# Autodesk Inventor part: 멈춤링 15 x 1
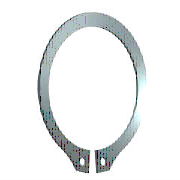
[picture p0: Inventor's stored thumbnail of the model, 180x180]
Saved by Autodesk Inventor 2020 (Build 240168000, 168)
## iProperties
Created: 2012-02
Part Number: 멈춤링 15 x 1
Material: 강철, 연강
Description: 리테이닝 링(C형)
Document SubType Name: Modeling
Standard: KS B 1336
Designer: mduedu
Standards Organization: KS
Language: ko-KR
Size Designation: 15 x 1
Categories: <MemberInstance><Categories><Category DisplayName="샤프트 부품" InternalName="7f7aeb1f-a693-4053-b835-cee3144e0d98" Mnemonic="SHFT"><Category DisplayName="써클립" Inter
Density: 1 g/cm^3
Appearance: 파란색 - 벽 페인트 - 광택
IsCustomPart: 1
Author: mduedu
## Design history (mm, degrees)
sketch "스케치1"
  geometry: L1 (-6, 0)-(6, 0) reference; L2 (0, 20.189)-(0, -80.536) reference; L3 (-48.09, 0)-(48.09, 0) reference; L4 (-0.425, -14.637)-(-0.425, -18.137); L5 (-0.425, -6.54)-(-0.425, -13.29); L6 (-2.795, 2.1)-(3.672, 2.1); L7 (0.425, -6.54)-(0.425, -13.29); L8 (0.425, -14.637)-(0.425, -18.137); C1 r 0.85 at (-1.7, -16.283); C2 r 0.85 at (1.7, -16.283); A1 r 7.15 centre (0, -7.5) between (0.425, -14.637) and (-0.425, -14.637); A2 r 9.075 centre (0, -6.975) between (4.291, -14.971) and (-4.291, -14.971); A3 r 10.646 centre (0, -7.5) between (-2.023, -17.952) and (-0.425, -18.137); A4 r 1.7 centre (-1.7, -16.283) between (-3.397, -16.376) and (-2.023, -17.952); A5 r 1.7 centre (-5.095, -16.469) between (-3.397, -16.376) and (-4.291, -14.971); A6 r 1.7 centre (5.095, -16.469) between (4.291, -14.971) and (3.397, -16.376); A7 r 1.7 centre (1.7, -16.283) between (2.023, -17.952) and (3.397, -16.376); A8 r 10.646 centre (0, -7.5) between (0.425, -18.137) and (2.023, -17.952)
  constraints: 16 point on circle, 12 end point, 10 centre point, 9 symmetric about line, 5 point on line, 4 tangent, 3 coincident, 2 horizontal, 1 perpendicular, 1 vertical, 5 other
  dimensions: "d0" = 14.3 diameter of A1 (= ND); "d1" = 3.5 distance of L4.end L4.start (= SRB2); "d6" = 0.425 distance between parallel lines of L2 L5 (= 0.25 x SD5); "d7" = 2.1 distance between parallel lines of L6 L3 (= SRB1); "d8" = 0.525 distance of A1.centre A2.centre (= 0.25 x SRB1); "d9" = 1.7 radius of A4 (= SD5); "d10" = 1.7 radius of A5 (= SD5); "d11" = 1.275 distance from line of L4 A4.centre (= 0.75 x SD5); "d12" = 1.7 diameter of C1 (= SD5); "d13" = 1.7 diameter of C2 (= SD5); "d14" = 7.5 distance from line of A1.centre L1 (= 0.5 x WD)
extrude "본체" new body sketch "스케치1" distance "d2" = 1 (= SD); taper "d3" = 0 deg
workaxis "Work Axis1"
workplane "Work Plane1"
body "Solid1"
other parameters: "WD" = 15 (= WDMIN) [user parameter; used in 1 equation term], "SD" = 1 [user parameter; used in 1 equation term], "SRB1" = 2.1 [user parameter; used in 2 equation terms], "ND" = 14.3 [user parameter; used in 1 equation term], "SRB2" = 3.5 [user parameter; used in 1 equation term], "SD5" = 1.7 [user parameter; used in 6 equation terms], "d15" = 0, "d16" = 0, "d17" = 0, "d41" = 0, "d42" = 0, "WDMIN" = 15 [user parameter; used in 1 equation term], "SD3" = 13.8 [user parameter], "WDMAX" = 16 [user parameter]
